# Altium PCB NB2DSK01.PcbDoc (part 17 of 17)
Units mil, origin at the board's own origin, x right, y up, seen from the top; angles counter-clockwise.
Board outline 11815 x 6500.03 mil, 8 copper layers (Top Layer, MidLayer1, MidLayer2, GND, PWR, MidLayer3, MidLayer4, Bottom Layer), stack 74.62 mil thick; 798 components, 1002 nets, 3927 pads, 3182 vias.
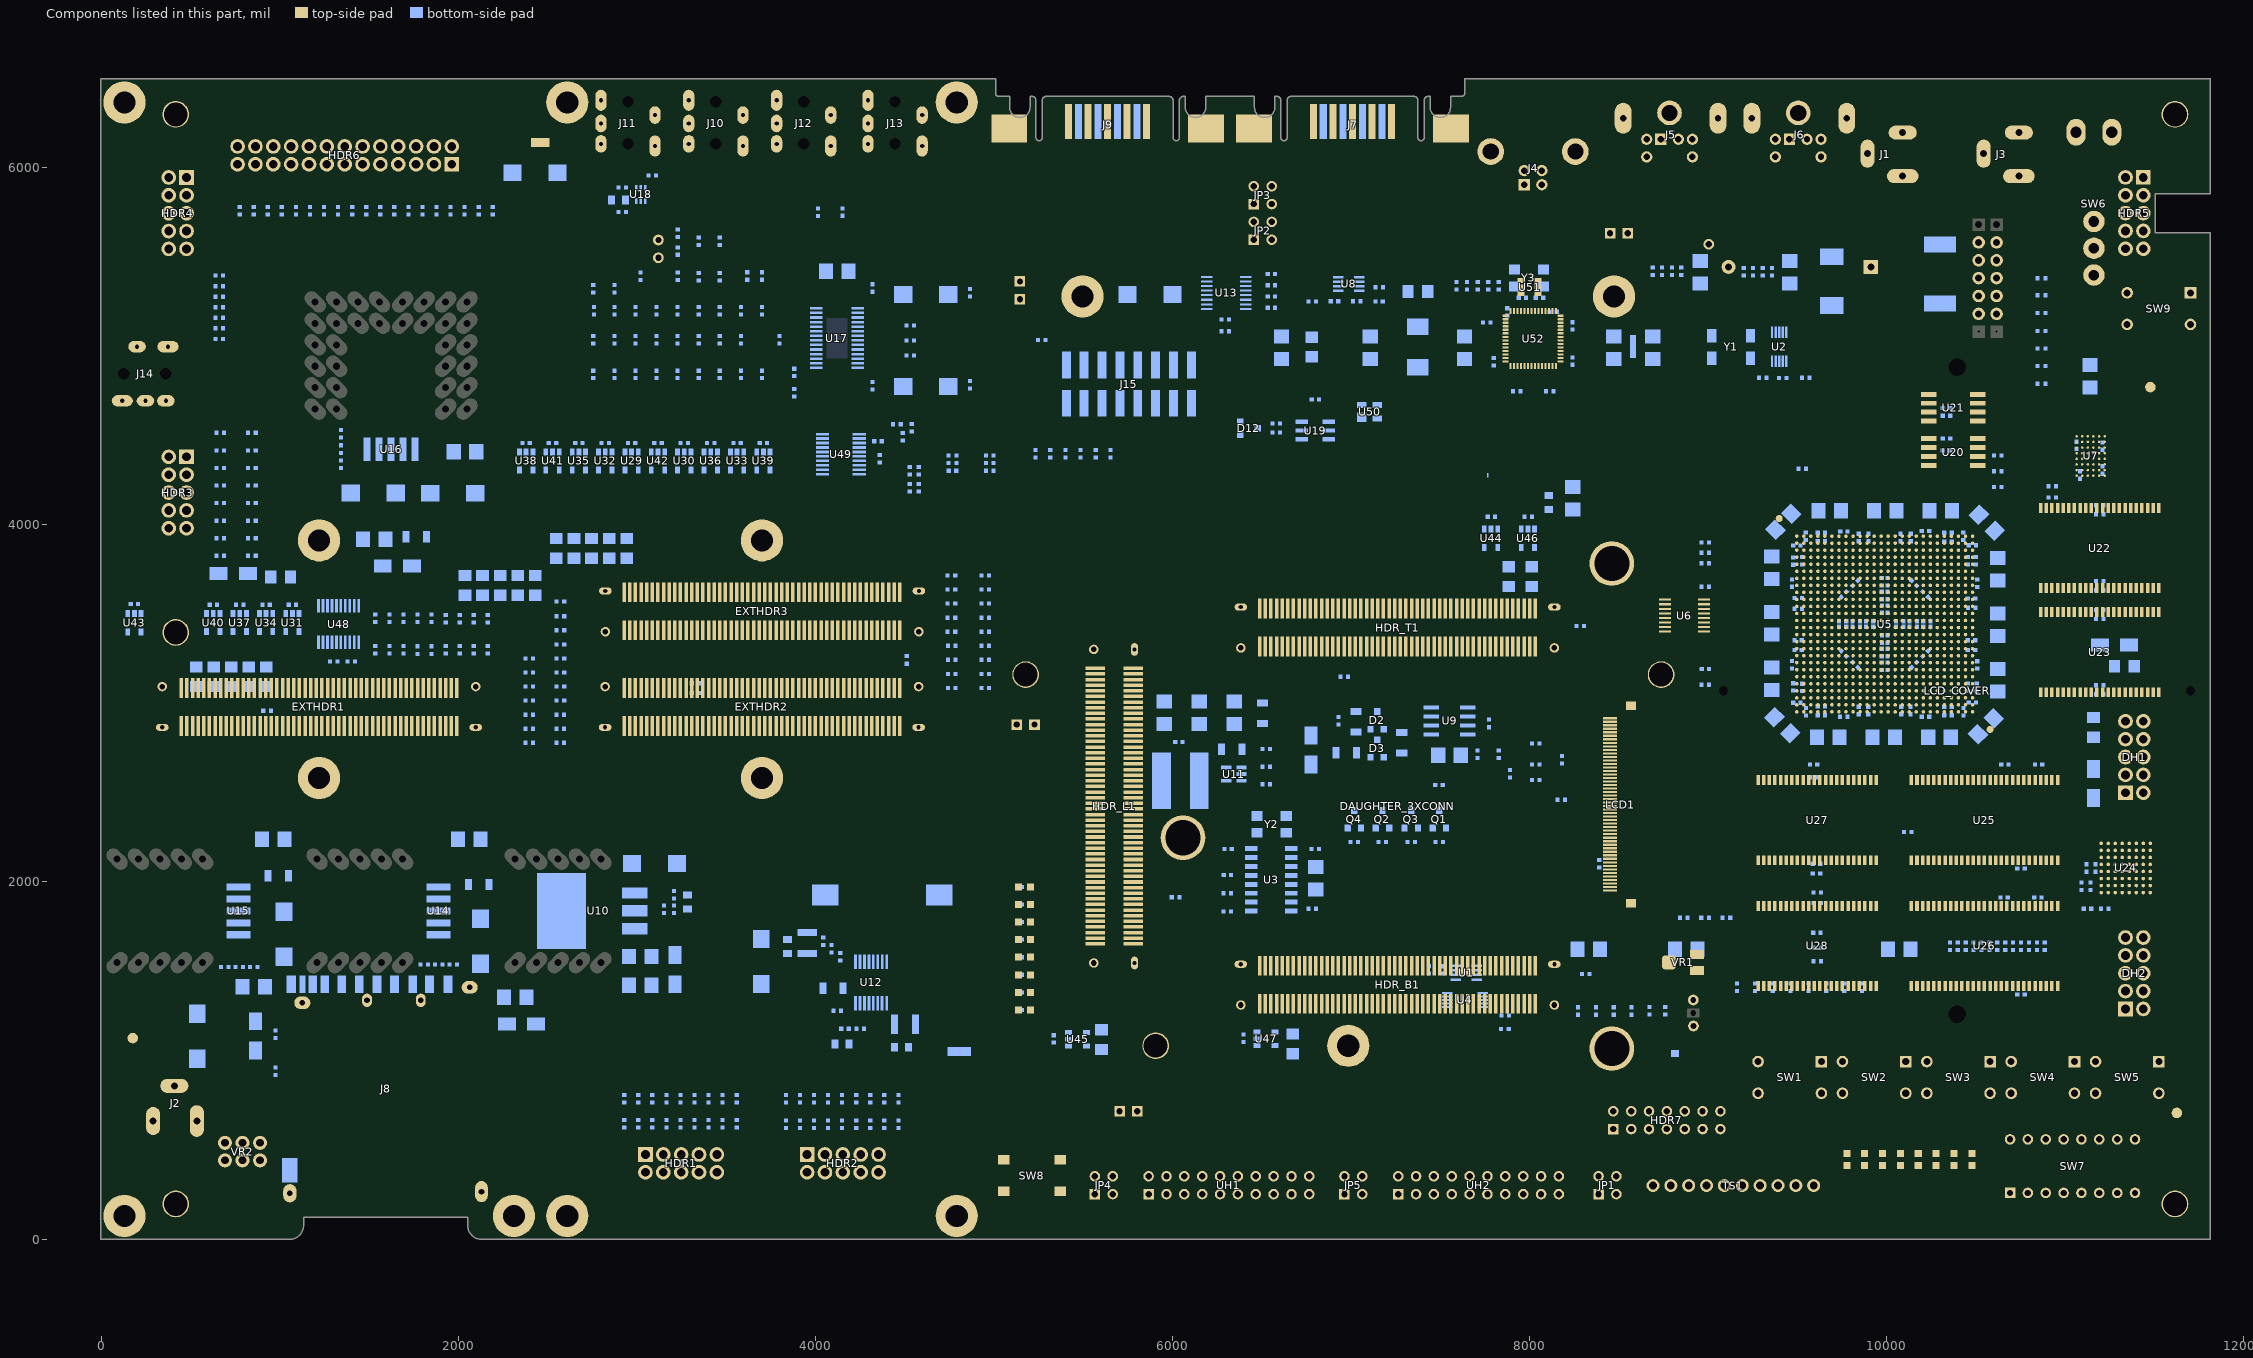
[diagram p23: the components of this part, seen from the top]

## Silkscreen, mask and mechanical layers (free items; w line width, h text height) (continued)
6. Fabrication Notes:
  drawing of 1666 lines, arcs and shapes, not listed
  text "1" at -314.94,10439.41 h118
  text "2" at 2519.06,10439.41 h118
  text "3" at 5354.06,10439.41 h118
  text "4" at 8070.06,10439.41 h118
  text "5" at 10905.06,10439.41 h118
  text "6" at 13661.06,10439.41 h118
  text "7" at 16496.06,10439.41 h118
  text "8" at 19409.06,10439.41 h118
  text "DESIGN INFORMATION" at 15492.06,10277.77 h79
  text "PRODUCT FAMILY" at -1394.28,10247.94 h118.11
  text "DRAWING ID/MODEL." at 1499.42,10247.94 h118.11
  text "(REFER ALSO PROFILING INFORMATION)" at 18009.06,10128.77 h69
  text "BOARD TECHNOLOGY" at 15492.06,10119.77 h75
  text "BOARD SIZE" at 17323.06,10119.77 h75
  text "4 TRACK" at 15486.86,9999.98 h69
  text "24 VIA" at 16051.86,9999.98 h69
  text "4 SPACE" at 16551.86,9999.98 h69
  text "300mm" at 17322.61,9991.95 h69
  text "165mm" at 18066.7,9991.95 h69
  text "X" at 17942.03,9984.27 h69
  text "NANOBOARD" at -780.94,9941.41 h120
  text "NB2DSK01.08" at 2377.81,9937.89 h140
  text "(MIN. TRACK / PADS / CLEARANCE" at 15494.06,9813.77 h69
  text "IN 0.001\" )" at 17265.06,9813.77 h69
  text "EXTERNAL" at 17546.06,9693.77 h69
  text "PER IPC-D-275 CLASS 2" at 18098.06,9693.77 h69
  text "LEVEL C AND IS THE" at 19426.06,9693.77 h69
  text "MINIMUM ANNULAR RING 0.05MM" at 15494.06,9692.77 h69
  text "(0.002\")" at 17088.06,9692.77 h69
  text "LAYER STACK CONFIGURATION" at 6836.2,9682.9 h49.21
  text "MANUFACTURING REGISTRATION" at 15499.06,9575.77 h69
  text "ALLOWANCE" at 17054.06,9575.77 h69
  text "BUILD CONFIGURATION AND SPECIFICATIONS SUMMARY" at 11029.67,9573.32 h80
  text "8 LAYER BUILD" at 7051.1,9411.9 h49.21
  text "8 Layer Build" at 11108.57,9403.82 h60
  text "Silk-Screened White Legend" at 12874.57,9403.82 h60
  text "5 Thou Tracks / 5 Thou Spacing" at 11108.57,9293.82 h60
  text "DO NOT TRIM Legend (Silkscreen)" at 12874.57,9293.82 h60
  text "BUILD STATISTICS" at 128.84,9268.04 h60
  text "BUILD STATISTICS" at 128.84,9268.04 h60
  text "8" at 20232.28,9196.85 h69
  text "CIRCUIT TYPE:" at 15492.06,9195.77 h75
  text "SS" at 16492.18,9195.77 h69
  text "DS" at 17243.06,9195.77 h69
  text "PTH MULTILAYER" at 18050.06,9195.77 h69
  text "Number of Layers :" at 19114.06,9195.77 h69
  text "X" at 17897.64,9192.91 h69
  text "24 Thou Via / 0.30mm Hole" at 11108.57,9183.82 h60
  text "Board Thickness Approx 1.7mm" at 12874.57,9183.83 h60
  text "A" at -1614.94,9179.41 h118
  text "A" at 20590.06,9179.41 h118
  text "GENERAL" at 120.84,9122.04 h40
  text "GENERAL" at 120.84,9122.04 h40
  text "-  COPPER CLAD" at 7793.54,9079.75 h29.53
  text "-  35 Micron H.T.E" at 8221.54,9079.75 h29.53
  text "TL" at 6748.01,9074.75 h49.21
  text "1 Oz Copper Clad" at 11108.57,9073.82 h60
  text "BOARD OUTLINE Layer Denotes Board Cutout" at 12874.57,9073.82 h60
  text "TOP LAYER" at 6246.77,9051.75 h49.21
  text ".Net_Count" at 501.84,9039.04 h40
  text ".Net_Count" at 501.84,9039.04 h40
  text "NETS" at 123.84,9037.04 h35
  text "NETS" at 123.84,9037.04 h35
  text "-  PRE-PREG" at 7818.54,9024.75 h29.53
  text "-  1080" at 8221.54,9023.75 h29.53
  text "FINGER CONNECTOR DIM PER:" at 15492.06,9018.77 h75
  text "AS SHOWN" at 19114.06,9018.77 h69
  text "-  PRE-PREG" at 7818.54,8979.82 h29.53
  text "-  1080" at 8221.54,8978.75 h29.53
  text "3um Immersion Gold" at 11108.57,8963.82 h60
  text "Must be BBT (Bare Board Tested)" at 12874.57,8963.82 h60
  text ".Component_Count" at 501.84,8957.04 h40
  text ".Component_Count" at 501.84,8957.04 h40
  text "COMPONENTS" at 124.84,8956.04 h35
  text "COMPONENTS" at 124.84,8956.04 h35
  text "MID LAYER 1" at 6246.78,8933.31 h49.21
  text "L1" at 6748,8929.81 h49.21
  text "-  35 Micron H.T.E" at 8221.54,8927.75 h29.53
  text "-  COPPER CLAD" at 7792.77,8927.65 h29.53
  text "-  CORE" at 7818.54,8874.82 h29.53
  text "-  0.25mm 35/35" at 8221.54,8874.75 h29.53
  text "No. OFF TOTAL" at 16516.06,8860.77 h69
  text "Gloss Black Solder Mask" at 11108.57,8853.82 h60
  text "Include BBT Certificate with Order" at 12874.57,8853.82 h60
  text "BOTH SIDES" at 19114.06,8842.27 h69
  text "ONE SIDE" at 18051.06,8840.77 h69
  text "-  35 Micron H.T.E" at 8221.54,8820.75 h29.53
  text "-  COPPER CLAD" at 7792.77,8820.15 h29.53
  text "PRIMITIVES" at 121.84,8819.04 h40
  text "PRIMITIVES" at 121.84,8819.04 h40
  text "MID LAYER 2" at 6247.69,8812.84 h49.21
  text "L2" at 6747.69,8812.84 h49.21
  text "-  1080" at 8221.54,8770.75 h29.53
  text "-  PRE-PREG" at 7817.77,8769.2 h29.53
  text ".Fill_Count" at 501.84,8735.04 h40
  text ".Fill_Count" at 501.84,8735.04 h40
  text "FILLS" at 124.84,8734.04 h35
  text "FILLS" at 124.84,8734.04 h35
  text "Include All BBT Failed Boards With Order" at 11109.57,8731.82 h60
  text "-  PRE-PREG" at 7817.77,8724.27 h29.53
  text "-  1080" at 8221.54,8723.75 h29.53
  text "P1" at 6747.69,8672.84 h49.21
  text "-  COPPER CLAD" at 7792.01,8672.1 h29.53
  text "-  35 Micron H.T.E" at 8221.54,8670.75 h29.53
  text "INTERNAL PLANE 1" at 6062.99,8669.29 h49.21
  text ".Track_Count" at 501.84,8654.04 h40
  text ".Track_Count" at 501.84,8654.04 h40
  text "TRACKS" at 124.84,8652.04 h35
  text "TRACKS" at 124.84,8652.04 h35
  text "FEED THRU'" at 16527.24,8645.27 h69
  text "TENTED" at 17480.06,8645.27 h69
  text "VIAS:" at 15492.06,8643.77 h75
  text "BURIED LAYER SEQUENCE" at 18425.06,8643.77 h69
  text "NONE" at 15987.41,8642.75 h69
  text "X" at 17303.06,8643.27 h69
  text "X" at 16337.21,8641.77 h69
  text "-  CORE" at 7817.77,8619.27 h29.53
  text "-  0.25mm 35/35" at 8221.54,8618.75 h29.53
  text ".String_Count" at 501.84,8572.04 h40
  text ".String_Count" at 501.84,8572.04 h40
  text "STRINGS" at 124.84,8570.04 h35
  text "STRINGS" at 124.84,8570.04 h35
  text "-  COPPER CLAD" at 7792.01,8564.6 h29.53
  text "-  35 Micron H.T.E" at 8221.54,8563.75 h29.53
  text "P2" at 6746.94,8557.29 h49.21
  text "INTERNAL PLANE 2" at 6062.99,8555.12 h49.21
  text "-  1080" at 8221.54,8513.75 h29.53
  text "-  PRE-PREG" at 7817.01,8513.65 h29.53
  text ".Arc_Count" at 501.84,8489.04 h40
  text ".Arc_Count" at 501.84,8489.04 h40
  text "ARC'S" at 124.84,8487.04 h35
  text "ARC'S" at 124.84,8487.04 h35
  text "-  PRE-PREG" at 7817.01,8468.73 h29.53
  text "-  1080" at 8221.54,8468.75 h29.53
  text "UNIQUE DRILL" at 16527.24,8448.27 h69
  text "2 SIZES" at 17480.06,8446.77 h69
  text "BLIND LAYER SEQUENCE" at 18425.06,8446.77 h69
  text "X" at 16337.06,8444.27 h69
  text "MID LAYER 3" at 6246.94,8417.27 h49.21
  text "L3" at 6746.94,8417.27 h49.21
  text "-  35 Micron H.T.E" at 8221.54,8416.75 h29.53
  text "-  COPPER CLAD" at 7791.25,8416.55 h29.53
  text "LANDS" at 120.84,8368.04 h40
  text "LANDS" at 120.84,8368.04 h40
  text "-  CORE" at 7817.01,8363.73 h29.53
  text "-  0.25mm 35/35" at 8221.54,8363.75 h29.53
  text "-  COPPER CLAD" at 7791.25,8309.05 h29.53
  text "-  35 Micron H.T.E" at 8221.54,8308.75 h29.53
  text "MID LAYER 4" at 6246.19,8301.74 h49.21
  text "L4" at 6746.19,8301.74 h49.21
  text ".Pad_Count" at 501.84,8284.04 h40
  text ".Pad_Count" at 501.84,8284.04 h40
  text "PADS" at 124.84,8282.04 h35
  text "PADS" at 124.84,8282.04 h35
  text "X" at 18964.06,8271.27 h69
  text "AS SHOWN" at 19114.06,8271.27 h69
  text "LAYER CONSTRUCTION PER:" at 15492.06,8269.77 h75
  text "LAMINATION SEQUENCE" at 17303.06,8269.77 h69
  text "-  PRE-PREG" at 7816.25,8258.11 h29.53
  text "-  1080" at 8221.54,8257.75 h29.53
  text "-  PRE-PREG" at 7816.25,8213.18 h29.53
  text "-  1080" at 8221.54,8210.75 h29.53
  text ".Via_Count" at 501.84,8202.04 h40
  text ".Via_Count" at 501.84,8202.04 h40
  text "VIA'S" at 125.84,8201.04 h35
  text "VIA'S" at 125.84,8201.04 h35
  text "BL" at 6746.18,8161.73 h49.21
  text "-  35 Micron H.T.E" at 8221.54,8161.75 h29.53
  text "BOTTOM LAYER" at 6169.29,8161.42 h49.21
  text "-  COPPER CLAD" at 7790.49,8161 h29.53
  text "NB2DSK01" at 18987.53,8102.19 h70
  text "FILE NAME:" at 18440.4,8090.49 h69
  text "X" at 17894.06,8076.27 h69
  text "CAD" at 18051.06,8075.27 h69
  text "ARTWORK:" at 15492.06,8073.77 h75
  text "MANUAL" at 16491.87,8073.77 h69
  text "DIGITISED" at 17244.06,8073.77 h69
  text "PRINT SCALE" at 117.84,8051.04 h40
  text "PRINT SCALE" at 117.84,8051.04 h40
  text "GERBER SET" at 18987.53,7988.01 h69
  text "FILE TYPE:" at 18440.4,7985.49 h69
  text ".Print_Scale" at 499.84,7966.04 h40
  text ".Print_Scale" at 499.84,7966.04 h40
  text "SCALE" at 122.84,7965.04 h35
  text "SCALE" at 122.84,7965.04 h35
  text "SUPPLIED ARTWORK/PATTERN MASTER LIST" at 15492.06,7825.77 h79
  text "TOTAL BOARD THICKNESS: APPROX" at 6151.61,7823.95 h49.21
  text "1.7mm +/- 0.1mm" at 7464,7797 h160
  text "DRAWING No./CAD FILE REF." at 17345.06,7675.77 h69
  text "REVISION" at 19951.25,7670.27 h69
  text "DESCRIPTION" at 15709.06,7668.77 h69
  text "8" at 20122.44,7490.47 h69.02
  text "NB2DSK01" at 15574.02,7472.28 h69.02
  text "ALTIUM NANOBOARD DESKTOP VERSION 8" at 17194.02,7472.28 h69.02
  text "B" at -1594.94,6424.41 h118
  text "B" at 20610.06,6424.41 h118
  text "DRILL DRAWING" at 15726.49,4082.96 h69
  text "APERTURE TABLES\FILES ARE EMBEDDED" at 17335.49,4082.96 h69
  text "1" at 20121.36,4080.74 h69
  text "C" at -1594.94,3864.41 h118
  text "C" at 20610.06,3864.41 h118
  text "POLYIMIDE" at 18482.32,3801.3 h69
  text "FR4-01" at 16428.87,3798.41 h69
  text "FR4-04" at 17137.87,3798.41 h69
  text "FR4-08" at 17826.87,3798.41 h69
  text "ARLON" at 19223.87,3798.41 h69
  text "TUC-722" at 19931.87,3798.41 h69
  text "X" at 19739.86,3792.34 h69
  text "MATERIAL:" at 15493.45,3791.31 h75
  text "THICKNESS:" at 15984.06,3611.41 h69
  text "~0.8mm" at 16850.06,3611.41 h69
  text "1.2mm" at 17559.06,3611.41 h69
  text "2mm" at 18937.06,3611.41 h69
  text "3.2mm" at 19645.06,3611.41 h69
  text "1.7mm" at 18240.17,3607.47 h69
  text "X" at 18058,3606 h69
  text "X" at 16660.64,3436.25 h68.9
  text "IN A/W ANSI IPC-6012 TYPE 3 CLASS 2" at 16850.08,3434.92 h69.02
  text "TOLERANCE:" at 15945.06,3433.41 h69
  text "OTHER +/-" at 19173.06,3433.41 h69
  text "X" at 16659.06,3258.91 h69
  text "IN A/W ANSI IPC-6012 TYPE 3 CLASS 2" at 16850.08,3257.91 h69.02
  text "BOW & TWIST:" at 15827.06,3256.41 h69
  text "AS SHOWN" at 19173.06,3256.41 h69
  text "COPPER THICKNESS (FINISHED)" at 15669.06,3078.41 h69
  text "18um (1/2oz)" at 16850.06,2902.91 h69
  text "OUTER:" at 16181.06,2901.41 h69
  text "35um (1oz)" at 18051.06,2901.41 h69
  text "70um (2oz)" at 19173.06,2901.41 h69
  text "X" at 17861.03,2898.41 h69
  text "18um (1/2oz)" at 16850.06,2725.91 h69
  text "INNER SIGNAL:" at 15846.06,2724.41 h69
  text "35um (1oz)" at 18051.06,2724.41 h69
  text "70um (2oz)" at 19173.06,2724.41 h69
  text "X" at 17861.03,2721.41 h69
  text "18um (1/2oz)" at 16850.06,2549.91 h69
  text "INNER PWR:" at 15964.06,2548.41 h69
  text "35um (1oz)" at 18051.06,2548.41 h69
  text "70um (2oz)" at 19173.06,2548.41 h69
  text "X" at 17861.03,2545.41 h69
  text "STRUCTURE:" at 15512.06,2351.41 h75
  text "REFER" at 16850.23,2351.41 h69
  text "AS SHOWN" at 19173.06,2175.91 h69
  text "X" at 18979.06,2174.91 h69
  text "AS PER DRAWING No." at 16850.06,2174.41 h69
  text "DRILLING:" at 15512.06,2016.41 h75
  text "X" at 16664.06,1880.91 h69
  text "COMPONENT SIDE" at 16850.06,1880.91 h69
  text "VIEWED FROM:" at 15846.06,1879.41 h69
  text "SOLDER SIDE" at 18051.06,1879.41 h69
  text "X" at 16664.06,1704.91 h69
  text "X" at 19489.06,1704.91 h69
  text "AS SHOWN" at 16850.06,1702.91 h69
  text "NC_ DRILL FILES" at 19685.06,1702.91 h69
  text "REFERENCE:" at 15945.06,1701.41 h69
  text "PATTERN MASTER LIST" at 18051.06,1701.41 h69
  text "20um" at 18051.06,1524.91 h69
  text "X" at 17859.06,1523.91 h69
  text "PTH MINIMUM COPPER THICKNESS:" at 16082.06,1523.41 h69
  text "OTHER" at 19173.06,1523.41 h69
  text "NPTH:" at 16220.06,1345.41 h69
  text "TENTED" at 16850.06,1345.41 h69
  text "PADS REMOVED" at 18051.06,1345.41 h69
  text "REMOVE PADS" at 19173.06,1345.41 h69
  text "NONE" at 19680.94,1168.91 h69
  text "2nd DRILL" at 16850.06,1167.41 h69
  text "BOTH" at 18051.06,1167.41 h69
  text "X" at 18451.53,1166.77 h69
  text "AS SHOWN" at 18641.57,1167.41 h69
  text "D" at -1594.94,1148.41 h118
  text "D" at 20610.06,1148.41 h118
  text "ETCHING" at 16850.06,951.91 h69
  text "BOARD FINISH:" at 15512.06,950.41 h75
  text "REFER PATTERN MASTER LIST" at 18051.06,950.41 h69
  text "X" at 18455.06,775.91 h69
  text "X" at 19499.06,775.91 h69
  text "COMPONENT" at 18641.06,773.91 h69
  text "SOLDER" at 19685.06,773.91 h69
  text "LEGEND / SCREEN PRINT:" at 16082.06,772.41 h69
  text "NONE" at 17756.06,772.41 h69
  text "mm" at -1849.94,754.41 h79 r90
  text "WHITE" at 16850.06,596.91 h69
  text "COLOUR:" at 16082.06,595.41 h69
  text "YELLOW" at 18051.06,595.41 h69
  text "OTHER" at 19173.06,595.41 h69
  text "X" at 16656.82,594.07 h69
  text "SCREEN PRINT" at 18641.06,400.91 h69
  text "SOLDER RESIST:" at 15768.06,399.41 h69
  text "LIQUID PHOTOIMAGEABLE" at 16850.06,399.41 h69
  text "X" at 18451.03,396.41 h69
  text "MATTE" at 17439.03,222.77 h69
  text "BLACK" at 19659.03,222.77 h69
  text "COLOUR:" at 16082.06,221.41 h69
  text "GLOSS" at 16850.06,221.41 h69
  text "BLUE" at 18641.06,221.41 h69
  text "G/Y" at 19173.06,221.41 h69
  text "X" at 16660.03,218.41 h69
  text "GREEN" at 18046.32,218.21 h69
  text "X" at 19495.03,218.41 h69
  text "TRACK FINISH:" at 15512.06,25.41 h75
  text "SELECTIVE SOLDER" at 16850.06,25.41 h69
  text "REFLOW SOLDER" at 18405.06,25.41 h69
  text "Radius 2.0mm" at 1392,-87 h39.37
  text "HASL (HOT AIR SOLDER LEVEL)" at 16850.36,-161.33 h69
  text "REFER PATTERN MASTER LIST" at 16850.06,-327.59 h69
  text "OTHER" at 18633.82,-327.59 h69
  text "3um IMMERSION GOLD SMOBC (SOLDER MASK OVER BARE COPPER)" at 16850.06,-524.09 h69
  text "X" at 16661.12,-529.41 h69
  text "HARD GOLD PLATE FINISH" at 16850.06,-702.59 h69
  text "OTHER" at 18405.06,-702.59 h69
  text "AS SHOWN" at 16850.06,-879.59 h69
  text "REFER" at 18405.06,-879.59 h69
  text "X" at 16659.06,-1074.09 h69
  text "CUT AND TRIM ACCORDING TO LAYER MECHANICAL 1 (BOARD OUTLINE)" at 16850.06,-1076.09 h69
  text "PROFILING:" at 15512.06,-1077.59 h75
  text "REFER PCB BLANK DWG No." at 16850.06,-1253.59 h69
  text "USE PROFILE/ ROUTE TAPE SUPPLIED" at 16850.06,-1430.59 h69
  text "(REFER PATTERN MASTER LIST)" at 18680.32,-1431.39 h69
  text "E" at -1594.94,-1509.59 h118
  text "E" at 20610.06,-1509.59 h118
  text "SQUARE CUT" at 16850.06,-1607.09 h69
  text "X" at 17625.03,-1609.23 h69
  text "N.C. ROUTE" at 17815.06,-1608.59 h69
  text "V. SCORE" at 18681.06,-1608.59 h69
  text "BLANK" at 19488.06,-1608.59 h69
  text "ACCEPTABILITY:" at 15492.06,-1805.59 h75
  text "MATERIALS AND WORKMANSHIP FOR" at 16653.06,-1805.59 h69
  text "ALL PRINTED WIRING BOARDS TO MEE" at 18425.06,-1805.59 h69
  text "T" at 20216.06,-1806.59 h69
  text "OR EXCEED THE REQUIREMENTS OF:" at 16634.06,-1923.59 h69
  text "X" at 16660.57,-2074.09 h69
  text "IN A/W ANSI IPC-A-600F" at 16849.57,-2080.09 h69
  text "2" at 18937.57,-2080.09 h69
  text "1" at 18622.57,-2081.59 h69
  text "3" at 19291.57,-2081.59 h69
  text "X" at 18786.62,-2085.41 h69
  text "UL CERTIFICATION" at 16849.57,-2259.59 h69
  text "AUSTEL" at 18661.57,-2259.59 h69
  text "A" at 17992.64,-2435.92 h69
  text "B" at 18307.64,-2435.92 h69
  text "MIL-P-55110E GRP" at 16849.57,-2436.59 h69
  text "AS2546" at 18655.97,-2436.59 h69
  text "OTHER" at 19448.97,-2436.59 h69
  text "ADDITIONAL REQUIREMENTS:" at 15489.06,-2596.59 h75
  text "NONE" at 16849.57,-2730.09 h69
  text "MICROSECTION:" at 15748.06,-2731.59 h69
  text "SAMPLE PLAN" at 17381.83,-2731.59 h69
  text "MIL-P-55110E SERIAL Nos. PER ORDER" at 18405.51,-2731.59 h69
  text "X" at 16658.35,-2736.04 h69
  text "2" at 20117.06,-2908.09 h69
  text "MIL-P-55110E GRP" at 17381.06,-2909.03 h69
  text "A" at 18524.14,-2908.36 h69
  text "B" at 18839.14,-2908.36 h69
  text "CERTIFICATION:" at 15748.06,-2909.59 h69
  text "NONE" at 16849.57,-2909.59 h69
  text "IPC CLASS:" at 18995.06,-2909.59 h69
  text "1" at 19764.06,-2909.59 h69
  text "3" at 20433.06,-2909.59 h69
  text "X" at 19927.03,-2912.59 h69
  text "PER ORDER" at 19645.03,-3079.73 h69
  text "QUALITY RELEASE REPORT" at 17381.06,-3087.59 h69
  text "OTHER" at 19192.06,-3087.59 h69
  text "X" at 19004.81,-3095.8 h69
  text "X" at 18200.06,-3260.09 h69
  text "REQUIRED" at 18400.06,-3263.09 h69
  text "ELECTRICAL TEST: Bare Board" at 15748.06,-3264.59 h66.93
  text "NONE" at 17381.06,-3264.59 h69
  text "PER ORDER" at 19192.06,-3264.59 h69
  text "0" at -1849.94,-3300.59 h79 r90
  text "2 SIDES" at 18522.77,-3441.09 h69
  text "MIN. PITCH" at 19193.06,-3441.42 h69
  text "SURFACE MOUNT:" at 15748.06,-3442.59 h69
  text "NONE" at 17381.06,-3442.59 h69
  text "0.65MM" at 19888.73,-3443.52 h69
  text "1 SIDE" at 17945.03,-3444.73 h69
  text "X" at 18329.03,-3450.23 h69
  text "LEGEND" at 18523.06,-3617.09 h69
  text "MANUFACTURER'S ID/LOGO:" at 15748.06,-3618.59 h69
  text "NONE" at 17381.06,-3618.59 h69
  text "FOIL" at 17971.38,-3618.59 h69
  text "REFER" at 19193.06,-3618.59 h69
  text "X" at 18333.03,-3621.59 h69
  text "X" at 17489.06,-3795.09 h69
  text "IS09001/AS3901" at 17676.06,-3795.09 h69
  text "NONE" at 18997.06,-3796.59 h69
  text "MANUFACTURER'S ACCREDITATION:" at 15748.06,-3816.59 h69
  text "DO NOT" at -2223.94,-3851.59 h79
  text "SCALE" at -2204.94,-3989.59 h79
  text "X" at 17187.68,-3990.09 h69
  text "PER ORDER" at 17384.68,-3991.09 h69
  text "PACKAGING AND HANDLING:" at 15748.06,-3992.59 h69
  text "REFER" at 18400.06,-3992.59 h69
  text "DIMENSIONS" at -2342.94,-4186.59 h79
  text "F" at -1594.94,-4225.59 h118
  text "F" at 20610.06,-4225.59 h118
  text "SCALE:" at 18935.76,-4284.52 h70
  text "NANOBOARD - NB2DSK" at 12679.31,-4287.87 h60
  text "PRODUCT" at 11970.02,-4302.88 h70
  text "ALTIUM LIMITED." at 16104.2,-4305.4 h80
  text "DATE" at 14446.92,-4307.51 h70
  text "IN" at -2086.94,-4324.59 h79
  text "LEVEL 3 / 12A RODBOROUGH ROAD" at 16102.2,-4428.8 h70
  text ".Print_Scale" at 19332.03,-4458.73 h100
  text "MILLIMETRES" at -2361.94,-4481.59 h79
  text "HARDWARE DEVELOPMENT GROUP" at 12679.32,-4486.9 h60
  text "DRAWN" at 11970.02,-4500.51 h70
  text "11.NOV.07" at 14345.02,-4504.72 h70
  text "FRENCHS FOREST - SYDNEY 2086" at 16102.2,-4570.2 h70
  text "DATE:" at 18932.76,-4678.22 h70
  text "APPROVED" at 11970.02,-4694.51 h70
  text "S.HOWELL" at 12679.32,-4698.72 h60
  text "NSW AUSTRALIA" at 16102.2,-4701.6 h70
  text "11.NOV.07" at 14345.02,-4704.72 h70
  text ".Print_Date" at 19302.03,-4833.73 h100
  text "RELEASE VERSION" at 5536.93,-4888.74 h70
  text "8" at 5045.93,-4892.76 h70
  text "PRODUCTION AND LOGISTICS" at 12679.31,-4892.6 h60
  text "CUSTOMER" at 11970.02,-4901.73 h70
  text "Title:" at 15117.92,-4905.81 h80
  text "SHEET" at 18936.23,-5071.92 h70
  text "NB2DSK01.08 DESKTOP NANOBOARD" at 15132.03,-5078.74 h90
  text "REVISION" at 4896.91,-5089.75 h70
  text "DESCRIPTION OF TASK OR MODIFICATION" at 7718.91,-5089.75 h70
  text "DATE" at 11455.8,-5108.92 h70
  text "APPD" at 10865.25,-5111.17 h70
  text "A2" at 20287.92,-5197.51 h78.74
  text ".Pcb_File_Name" at 7189.02,-5277.69 h70
  text ".Printout_Name" at 5584.02,-5292.73 h70
  text "TEMPLATE: -" at 4896.91,-5294.75 h70
  text "1" at -314.94,-5505.59 h118
  text "2" at 2519.06,-5505.59 h118
  text "3" at 5354.06,-5505.59 h118
  text "4" at 8070.06,-5505.59 h118
  text "5" at 10905.06,-5505.59 h118
  text "6" at 13661.06,-5505.59 h118
  text "7" at 16496.06,-5505.59 h118
  text "8" at 19409.06,-5505.59 h118
7. Assembly - Top:
  circle w5: c11614.18,6299.3 r110.24
  lines w5: 0,3228.35 0,3267.72 0,6496.07
8. Assembly - Bottom:
  circle w7.87: c4385.83,1901.58 r216.54
  circle w7.87: c4385.83,1901.58 r285.43
  lines w1.97: 8354.33,4346.46 9512.87,4346.46 9535.43,4311.02 ; 9415.02,4235.46 cw(c9988.19,3444.88) 9665.07,4366.37 ; 9527.56,4318.9 9535.43,4311.02 ; 9531.5,4322.84 9535.43,4311.02
  lines w7.87: 4192.32,1675.82 4015.75,1803.15 4015.75,2000 4192.32,2127.33 ; 4346.46,1901.58 4425.2,1901.58 ; 4385.83,1862.21 4385.83,1940.95 ; 4575.4,1675.82 4751.97,1803.15 4751.97,2000 4575.4,2127.33
  text "RED" at 3000.63,5964.57 h62.99
  text "BLUE" at 4519.69,5964.57 h62.99
  text "BLACK" at 3528.19,5960.63 h62.99
  text "GREEN" at 4036.06,5960.63 h62.99
  text "BLACK" at 527.56,4937.01 h62.99 r90
  text "See Detail Drawing - FPGA Discretes" at 9507.87,4358.27 h78.74
15. Dimension-Mount:
  lines w3.94: 0,78.74 0,3228.35 ; 0,3267.72 0,6496.06
Drill Drawing:
  text ".Legend" at -1320.91,-5240.51 h68.9

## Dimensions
6984.25,1082.68 to 5673.23,1487.8 on 5. Daughter
6984.25,1082.68 to 6224.41,1523.23 on 5. Daughter
6984.25,1082.68 to 6322.83,3425.2 on 5. Daughter
6984.25,1082.68 to 5575.2,1389.77 on 5. Daughter
6984.25,1082.68 to 6322.83,1425.2 on 5. Daughter
6984.25,1082.68 to 8472.44,5279.53 on 5. Daughter
6984.25,1082.68 to 5496.06,5279.53 on 5. Daughter
6984.25,1082.68 to 8472.44,5279.53 on 5. Daughter
2255.91,2882.28 to 185.04,2882.29 on 5. Daughter
11811.02,6496.06 to 11614.17,6299.21 on 15. Dimension-Mount
417.32,3397.64 to 1134.12,121.47 on 15. Dimension-Mount
0,6496.06 to 417.32,6299.21 on 15. Dimension-Mount
417.32,6299.21 to 0,6496.06 on 15. Dimension-Mount
0,6496.06 to 5905.51,5279.53 on 15. Dimension-Mount
0,6496.06 to 11614.17,6299.21 on 15. Dimension-Mount
417.32,196.85 to 0,0 on 15. Dimension-Mount
8736.22,3161.42 to 0,6496.06 on 15. Dimension-Mount
0,0 to 5905.51,1082.68 on 15. Dimension-Mount
0,0 to 417.32,3397.64 on 15. Dimension-Mount
5905.51,1082.68 to 0,0 on 15. Dimension-Mount
5177.17,3161.42 to 0,0 on 15. Dimension-Mount
11614.17,196.85 to 11811.02,0 on 15. Dimension-Mount
0,0 to 417.32,196.85 on 15. Dimension-Mount
11811.02,0 to 0,0 on 15. Dimension-Mount
11811.02,0 to 5905.51,5279.53 on 15. Dimension-Mount
5177.17,3161.42 to 11811.02,0 on 15. Dimension-Mount
11811.02,0 to 11614.17,196.85 on 15. Dimension-Mount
